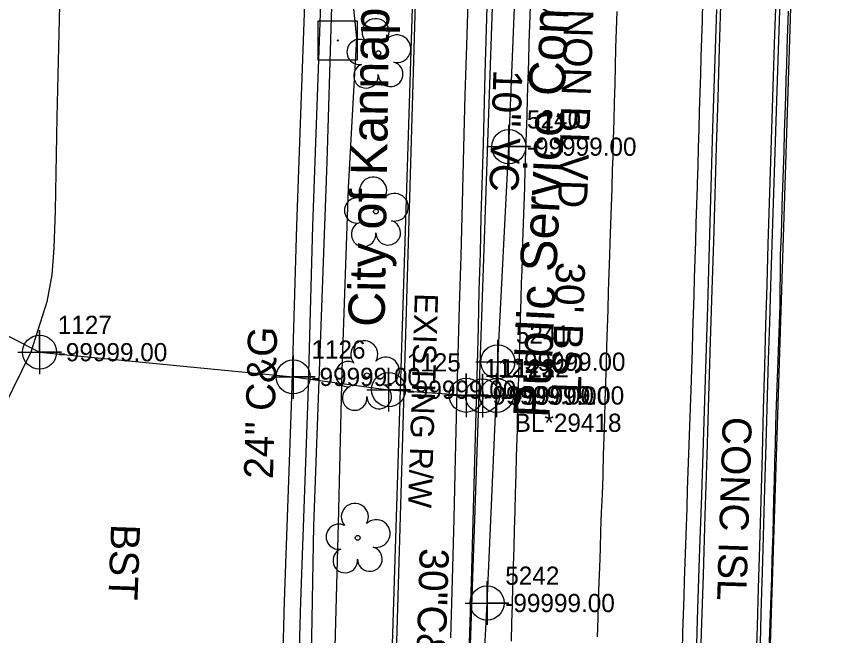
# Model space of a CAD drawing. Extents: x 1516784 to 1522736, y 634838 to 639369.
# Drawn here: x 1520333.4 to 1520444.6, y 637287.2 to 637372.3 of the extents above; entities that cross this region are included whole.
import ezdxf

# ---------------------------------------------------------------- set-up
doc = ezdxf.new("R2010")
doc.units = 0
for name, color, linetype in [('COGO Default Point Elevation', 7, 'Continuous'), ('COGO Default Point Number', 7, 'Continuous'), ('Exist Environmental Wetland Boundary Cogo Elevation', 7, 'Continuous'), ('Exist Environmental Wetland Boundary Cogo Number', 7, 'Continuous'), ('Exist Environmental Wetland Boundary Cogo Point CELL', 7, 'Continuous'), ('Exist Environmental Wetland Boundary Text', 7, 'Continuous'), ('Exist Right of Way Line', 7, 'Continuous'), ('Exist Right of Way Line Text', 7, 'Continuous'), ('Exist Roads Curbs Text', 7, 'Continuous'), ('Exist Roads EOP Other Text', 7, 'Continuous'), ('Exist Roads EOP Text', 7, 'Continuous'), ('Exist Utilities Gas UG Line SUE LOS B', 7, 'Continuous'), ('Exist Utilities Gas UG Line SUE LOS B Cogo Comment', 7, 'Continuous'), ('Exist Utilities Gas UG Line SUE LOS B Cogo Elevation', 7, 'Continuous'), ('Exist Utilities Gas UG Line SUE LOS B Cogo Number', 7, 'Continuous'), ('Exist Utilities Gas UG Line SUE LOS B Cogo Point CELL', 7, 'Continuous'), ('Exist Utilities Gas UG Line SUE LOS B Text', 7, 'Continuous'), ('Exist Utilities Other Pole With Base CELL', 7, 'Continuous'), ('Exist Utilities Sanitary Sewer UG Line', 7, 'Continuous'), ('Exist Utilities Sanitary Sewer UG Line Text', 7, 'Continuous'), ('Exist Utilities Water UG Line SUE LOS C', 7, 'Continuous'), ('Exist Utilities Water UG Line SUE LOS C Text', 7, 'Continuous'), ('Exist Vegetation Hedge Row', 7, 'Continuous'), ('Exist Vegetation Tree CELL', 7, 'Continuous'), ('Scratch_Level_5', 7, 'Continuous')]:
    doc.layers.add(name, color=color, linetype=linetype)

msp = doc.modelspace()

# ---------------------------------------------------------------- linework, layer by layer
at = {"layer": 'COGO Default Point Elevation'}
for points in [[(1520404.06, 637373.62), (1520403.98, 637371.12), (1520403.9, 637368.62), (1520403.82, 637366.13), (1520403.74, 637363.63), (1520403.67, 637361.13), (1520403.59, 637358.63), (1520403.51, 637356.32), (1520403.43, 637353.82), (1520403.35, 637351.32), (1520403.27, 637348.82), (1520403.18, 637346.33), (1520403.1, 637343.83), (1520403.02, 637341.33), (1520402.94, 637338.83), (1520402.85, 637336.34), (1520402.84, 637335.88), (1520402.77, 637333.38), (1520402.7, 637330.88), (1520402.63, 637328.38), (1520402.55, 637325.88), (1520402.48, 637323.39), (1520402.41, 637320.89), (1520402.34, 637318.39), (1520402.3, 637316.8), (1520402.23, 637314.31), (1520402.16, 637311.81), (1520402.09, 637309.31), (1520402.02, 637306.81), (1520401.94, 637304.32), (1520401.87, 637301.82), (1520401.8, 637299.32), (1520401.73, 637296.82), (1520401.66, 637294.32), (1520401.65, 637293.98), (1520401.58, 637291.48), (1520401.51, 637288.98), (1520401.43, 637286.48)], [(1520424.98, 637285.15), (1520425.06, 637287.65), (1520425.13, 637290.15), (1520425.21, 637292.64), (1520425.27, 637294.78), (1520425.36, 637297.27), (1520425.44, 637299.77), (1520425.53, 637302.27), (1520425.62, 637304.76), (1520425.7, 637307.26), (1520425.79, 637309.76), (1520425.88, 637312.26), (1520425.96, 637314.75), (1520426.05, 637317.25), (1520426.13, 637319.75), (1520426.22, 637322.25), (1520426.28, 637323.89), (1520426.35, 637326.39), (1520426.43, 637328.89), (1520426.51, 637331.39), (1520426.58, 637333.88), (1520426.66, 637336.38), (1520426.73, 637338.88), (1520426.81, 637341.38), (1520426.89, 637343.87), (1520426.96, 637346.37), (1520427.04, 637348.87), (1520427.05, 637349.26), (1520427.13, 637351.75), (1520427.2, 637354.25), (1520427.28, 637356.75), (1520427.35, 637359.25), (1520427.43, 637361.75), (1520427.51, 637364.24), (1520427.58, 637366.74), (1520427.66, 637369.24), (1520427.73, 637371.74), (1520427.81, 637374.24)], [(1520415.95, 637372.93), (1520415.88, 637370.44), (1520415.81, 637367.94), (1520415.74, 637365.44), (1520415.68, 637362.94), (1520415.61, 637360.44), (1520415.54, 637357.95), (1520415.47, 637355.45), (1520415.4, 637352.95), (1520415.35, 637351.19), (1520415.27, 637348.69), (1520415.18, 637346.19), (1520415.09, 637343.7), (1520415.01, 637341.2), (1520414.95, 637339.48), (1520414.87, 637336.99), (1520414.8, 637334.49), (1520414.72, 637331.99), (1520414.64, 637329.49), (1520414.57, 637327), (1520414.49, 637324.5), (1520414.42, 637322), (1520414.34, 637319.5), (1520414.27, 637317), (1520414.19, 637314.51), (1520414.11, 637312.01), (1520414.04, 637309.51), (1520414.03, 637309.13), (1520413.94, 637306.63), (1520413.84, 637304.14), (1520413.75, 637301.64), (1520413.66, 637299.14), (1520413.57, 637296.65), (1520413.49, 637294.58), (1520413.42, 637292.09), (1520413.34, 637289.59), (1520413.27, 637287.09)], [(1520439.5, 637372.97), (1520439.43, 637370.47), (1520439.35, 637367.97), (1520439.27, 637365.47), (1520439.22, 637363.75), (1520439.14, 637361.25), (1520439.06, 637358.75), (1520438.98, 637356.26), (1520438.9, 637353.76), (1520438.82, 637351.26), (1520438.74, 637348.76), (1520438.66, 637346.27), (1520438.58, 637343.77), (1520438.5, 637341.27), (1520438.44, 637339.54), (1520438.42, 637337.04), (1520438.39, 637334.54), (1520438.38, 637332.57), (1520438.29, 637330.07), (1520438.19, 637327.58), (1520438.1, 637325.08), (1520438.01, 637322.58), (1520437.92, 637320.09), (1520437.83, 637317.59), (1520437.78, 637316.05), (1520437.71, 637313.55), (1520437.65, 637311.05), (1520437.59, 637308.55), (1520437.52, 637306.06), (1520437.46, 637303.56), (1520437.4, 637301.06), (1520437.37, 637300.18), (1520437.29, 637297.68), (1520437.21, 637295.19), (1520437.12, 637292.69), (1520437.04, 637290.19), (1520436.96, 637287.69), (1520436.88, 637285.44)]]:
    msp.add_lwpolyline(points, dxfattribs=at)
at = {"layer": 'COGO Default Point Number'}
for points in [[(1520398.09, 637373.57), (1520397.85, 637364.38), (1520397.58, 637354.8), (1520397.3, 637344.85), (1520397.17, 637339.74), (1520397.03, 637334.61), (1520396.9, 637329.53), (1520396.77, 637324.5), (1520396.52, 637314.57), (1520396.25, 637304.61), (1520395.96, 637294.64), (1520395.65, 637284.9)], [(1520438.37, 637374.4), (1520438.07, 637364.89), (1520437.75, 637355.05), (1520437.42, 637345.23), (1520437.09, 637335.29), (1520436.94, 637330.23), (1520436.79, 637325.1), (1520436.5, 637315.14), (1520436.22, 637305.87), (1520435.97, 637297.51), (1520435.77, 637290.29), (1520435.61, 637284.12), (1520435.48, 637278.91), (1520435.46, 637269.2), (1520435.57, 637263.31), (1520435.75, 637255.63), (1520435.97, 637247.03), (1520436.2, 637238.41), (1520436.43, 637229.54), (1520436.66, 637220.17), (1520436.89, 637210.51), (1520437.03, 637205.14)], [(1520424.34, 637205.04), (1520424.59, 637212.95), (1520424.86, 637221.22), (1520425.16, 637229.46), (1520425.44, 637237.75), (1520425.72, 637246.14), (1520425.99, 637254.71), (1520426.27, 637263.45), (1520426.54, 637272.17), (1520426.81, 637280.82), (1520427.08, 637289.4), (1520427.35, 637297.92), (1520427.64, 637306.53), (1520427.93, 637315.23), (1520428.2, 637323.88), (1520428.46, 637332.44), (1520428.7, 637340.75), (1520428.92, 637348.82), (1520429.17, 637356.92), (1520429.44, 637365.09), (1520429.71, 637373.22)]]:
    msp.add_lwpolyline(points, dxfattribs=at)
at = {"layer": 'Exist Environmental Wetland Boundary Cogo Elevation'}
msp.add_lwpolyline([(1520332.04, 637433.25), (1520340.94, 637432.87), (1520339.42, 637375.76), (1520339.01, 637358.42), (1520338.8, 637345.6), (1520338.58, 637340.45), (1520338.33, 637336.8), (1520337.65, 637333.07), (1520335.42, 637326.18), (1520330.32, 637315.81), (1520324.72, 637306.87), (1520317.62, 637297.56), (1520313.49, 637293.52), (1520309.75, 637291.34), (1520305.26, 637289.8), (1520300.34, 637289.03), (1520295.68, 637289.02), (1520291.65, 637289.38)], dxfattribs=at)
at = {"layer": 'Exist Environmental Wetland Boundary Cogo Number'}
for points in [[(1520375.34, 637376.51), (1520374.17, 637343.49), (1520373.49, 637319.99), (1520372.48, 637291.92), (1520371.83, 637267.31), (1520357.88, 637267.61), (1520356.33, 637267.53), (1520355.14, 637266.38), (1520354.69, 637264.71), (1520354.4, 637259.13)], [(1520437.85, 637375.73), (1520437.66, 637369.85), (1520437.47, 637364.01), (1520437.28, 637358.19), (1520437.09, 637352.41), (1520436.91, 637346.67), (1520436.74, 637341), (1520436.58, 637335.39), (1520436.42, 637329.86), (1520436.26, 637324.22), (1520436.1, 637318.34), (1520435.93, 637312.2), (1520435.75, 637305.81), (1520435.57, 637299.53), (1520435.4, 637293.75), (1520435.24, 637288.45), (1520434.95, 637279.56)], [(1520395.55, 637375.66), (1520395.31, 637368.33), (1520395.09, 637361.45), (1520394.9, 637354.23), (1520394.72, 637346.64), (1520394.53, 637339.37), (1520394.31, 637332.51), (1520394.12, 637325.81), (1520393.95, 637319.11), (1520393.77, 637311.6), (1520393.57, 637303.27), (1520393.34, 637294.96), (1520393.1, 637286.93)], [(1520425.34, 637218.9), (1520425.55, 637225.26), (1520425.76, 637231.73), (1520425.98, 637238.21), (1520426.2, 637244.69), (1520426.43, 637251.18), (1520426.65, 637257.84), (1520426.89, 637264.82), (1520427.12, 637272.12), (1520427.36, 637279.75), (1520427.61, 637287.61), (1520427.86, 637295.6), (1520428.11, 637303.72), (1520428.37, 637311.98), (1520428.63, 637320.06), (1520428.86, 637327.64), (1520429.08, 637334.74), (1520429.28, 637341.34), (1520429.48, 637347.77), (1520429.68, 637354.34), (1520429.89, 637361.05), (1520430.1, 637367.9), (1520430.33, 637375.28)]]:
    msp.add_lwpolyline(points, dxfattribs=at)
at = {"layer": 'Exist Environmental Wetland Boundary Cogo Point CELL'}
msp.add_lwpolyline([(1520376.57, 637480.17), (1520375.98, 637461.88), (1520375.36, 637442.8), (1520374.43, 637420.34), (1520373.76, 637395.96), (1520373.12, 637376.59), (1520371.96, 637343.56), (1520371.28, 637320.07), (1520370.26, 637291.99), (1520369.67, 637269.57), (1520357.85, 637269.82), (1520355.39, 637269.7), (1520353.16, 637267.55), (1520352.49, 637265.06), (1520352.21, 637259.8)], dxfattribs=at)
at = {"layer": 'Exist Environmental Wetland Boundary Text'}
msp.add_line((1520460.36, 638022.61), (1520433.58, 637175.96), dxfattribs=at)
at = {"layer": 'Exist Right of Way Line'}
msp.add_line((1520392.38, 637516.53), (1520383.93, 637249.27), dxfattribs=at)
at = {"layer": 'Exist Utilities Gas UG Line SUE LOS B'}
for points in [[(1520395.28, 637209.93), (1520395.83, 637233.81), (1520396.63, 637263.16), (1520398.14, 637291.72), (1520399.6, 637324.85), (1520401.12, 637354.38), (1520402.42, 637385.79)], [(1520308.77, 637341.99), (1520314.56, 637337.54), (1520336.64, 637326.16), (1520371.5, 637322.77), (1520384.6, 637321.01), (1520395.27, 637320.24), (1520397.5, 637320.17), (1520399.43, 637320.22)]]:
    msp.add_lwpolyline(points, dxfattribs=at)
at = {"layer": 'Exist Utilities Gas UG Line SUE LOS B Cogo Point CELL'}
for points in [[(1520398.12, 637354.38), (1520404.12, 637354.38), (1520401.12, 637354.38), (1520401.12, 637357.38), (1520401.12, 637351.38)], [(1520333.64, 637326.16), (1520339.64, 637326.16), (1520336.64, 637326.16), (1520336.64, 637329.16), (1520336.64, 637323.16)], [(1520396.6, 637324.85), (1520402.6, 637324.85), (1520399.6, 637324.85), (1520399.6, 637327.85), (1520399.6, 637321.85)], [(1520368.5, 637322.77), (1520374.5, 637322.77), (1520371.5, 637322.77), (1520371.5, 637325.77), (1520371.5, 637319.77)], [(1520381.6, 637321.01), (1520387.6, 637321.01), (1520384.6, 637321.01), (1520384.6, 637324.01), (1520384.6, 637318.01)], [(1520392.27, 637320.24), (1520398.27, 637320.24), (1520395.27, 637320.24), (1520395.27, 637323.24), (1520395.27, 637317.24)], [(1520394.5, 637320.17), (1520400.5, 637320.17), (1520397.5, 637320.17), (1520397.5, 637323.17), (1520397.5, 637317.17)], [(1520396.43, 637320.22), (1520402.43, 637320.22), (1520399.43, 637320.22), (1520399.43, 637323.22), (1520399.43, 637317.22)], [(1520395.14, 637291.72), (1520401.14, 637291.72), (1520398.14, 637291.72), (1520398.14, 637294.72), (1520398.14, 637288.72)]]:
    msp.add_lwpolyline(points, dxfattribs=at)
for centre in [(1520401.12, 637354.38), (1520336.64, 637326.16), (1520399.6, 637324.85), (1520371.5, 637322.77), (1520384.6, 637321.01), (1520395.27, 637320.24), (1520397.5, 637320.17), (1520399.43, 637320.22), (1520398.14, 637291.72)]:
    msp.add_circle(centre, 2.34, dxfattribs=at)
at = {"layer": 'Exist Utilities Other Pole With Base CELL'}
msp.add_line((1520377.63, 637368.97), (1520377.63, 637368.97), dxfattribs=at)
msp.add_lwpolyline([(1520374.91, 637371.67), (1520380.31, 637371.67), (1520380.31, 637366.27), (1520374.91, 637366.27), (1520374.91, 637371.67)], dxfattribs=at)
msp.add_circle((1520377.63, 637368.97), 0.0707, dxfattribs=at)
at = {"layer": 'Exist Utilities Sanitary Sewer UG Line'}
msp.add_line((1520401.19, 637442.63), (1520394.09, 637235.13), dxfattribs=at)
at = {"layer": 'Exist Utilities Water UG Line SUE LOS C'}
msp.add_lwpolyline([(1520382.58, 637189.84), (1520384.26, 637236.31), (1520393.57, 637554.04), (1520396.87, 637710.27)], dxfattribs=at)
at = {"layer": 'Exist Vegetation Hedge Row'}
for points in [[(1520356.47, 637266.55), (1520373.67, 637266.52), (1520374.33, 637302.32), (1520376.18, 637352.29), (1520377.35, 637391.98)], [(1520379.39, 637377.44), (1520380.21, 637369.28), (1520379.7, 637360.36), (1520379.03, 637348.72), (1520378.2, 637323.64), (1520377.68, 637302.65), (1520377.16, 637284.01), (1520376.63, 637271.06), (1520377.02, 637262.25), (1520375.52, 637257.71), (1520370.26, 637255.31), (1520365.22, 637255.35), (1520362.68, 637259.82), (1520362.01, 637263.57), (1520355.98, 637264.16), (1520356.47, 637266.55)]]:
    msp.add_lwpolyline(points, dxfattribs=at)
at = {"layer": 'Exist Vegetation Tree CELL'}
for p, q in [((1520383.2, 637367.23), (1520383.2, 637367.23)), ((1520382.87, 637345.47), (1520382.87, 637345.47)), ((1520381.64, 637322.99), (1520381.64, 637322.99)), ((1520380.36, 637300.67), (1520380.36, 637300.67))]:
    msp.add_line(p, q, dxfattribs=at)
for centre in [(1520383.2, 637367.23), (1520382.87, 637345.47), (1520381.64, 637322.99), (1520380.36, 637300.67)]:
    msp.add_circle(centre, 0.326, dxfattribs=at)
for centre, radius, start, end in [((1520382.82, 637370.1), 1.86, 330.1651, 219.7134), ((1520380.6, 637367.38), 1.73, 62.6636, 279.3457), ((1520385.75, 637367.82), 1.9, 257.1011, 134.1999), ((1520384.88, 637364.33), 1.7, 181.2822, 74.56), ((1520381.5, 637364.11), 1.69, 111.5671, 6.231), ((1520382.49, 637348.34), 1.86, 330.1651, 219.7134), ((1520385.42, 637346.06), 1.9, 257.1011, 134.1999), ((1520380.27, 637345.62), 1.73, 62.6636, 279.3457), ((1520381.17, 637342.35), 1.69, 111.5671, 6.231), ((1520384.55, 637342.57), 1.7, 181.2822, 74.56), ((1520381.26, 637325.86), 1.86, 330.1651, 219.7134), ((1520379.04, 637323.15), 1.73, 62.6636, 279.3457), ((1520384.19, 637323.58), 1.9, 257.1011, 134.1999), ((1520379.94, 637319.87), 1.69, 111.5671, 6.231), ((1520383.31, 637320.09), 1.7, 181.2822, 74.56), ((1520379.97, 637303.54), 1.86, 330.1651, 219.7134), ((1520377.75, 637300.82), 1.73, 62.6636, 279.3457), ((1520382.91, 637301.26), 1.9, 257.1011, 134.1999), ((1520378.65, 637297.55), 1.69, 111.5671, 6.231), ((1520382.03, 637297.77), 1.7, 181.2822, 74.56)]:
    msp.add_arc(centre, radius, start, end, dxfattribs=at)

# ---------------------------------------------------------------- texts
at = {"layer": 'Exist Right of Way Line Text'}
msp.add_text('EXISTING R/W', height=3.2, rotation=268.1887, dxfattribs=at).set_placement((1520388.22, 637334.29))
at = {"layer": 'Exist Roads Curbs Text'}
for s, rotation, p in [('24" C&G', 88.3471, (1520368.71, 637308.71)), ('CONC ISL', 268.197, (1520430.54, 637317.33)), ('30"C&G', 268.253, (1520388.9, 637299.29))]:
    msp.add_text(s, height=4, rotation=rotation, dxfattribs=at).set_placement(p)
at = {"layer": 'Exist Roads EOP Other Text'}
msp.add_text('BST', height=4, rotation=267.9794, dxfattribs=at).set_placement((1520346.47, 637302.6))
at = {"layer": 'Exist Roads EOP Text'}
msp.add_text("U2 29 S CANNON BLVD     30' BST", height=4, rotation=268.125, dxfattribs=at).set_placement((1520409.82, 637405.42))
at = {"layer": 'Exist Utilities Gas UG Line SUE LOS B Cogo Comment'}
msp.add_text('BL*29418', height=2.5, dxfattribs=at).set_placement((1520401.93, 637315.22))
at = {"layer": 'Exist Utilities Gas UG Line SUE LOS B Cogo Elevation'}
for p in [(1520403.62, 637353.13), (1520339.14, 637324.91), (1520402.1, 637323.6), (1520374, 637321.52), (1520387.1, 637319.76), (1520397.77, 637318.99), (1520400, 637318.92), (1520401.93, 637318.97), (1520400.64, 637290.47)]:
    msp.add_text('-99999.00', height=2.5, dxfattribs=at).set_placement(p)
at = {"layer": 'Exist Utilities Gas UG Line SUE LOS B Cogo Number'}
for s, p in [('5240', (1520403.62, 637356.88)), ('1127', (1520339.14, 637328.66)), ('5241', (1520402.1, 637327.35)), ('1126', (1520374, 637325.27)), ('1125', (1520387.1, 637323.51)), ('1124', (1520397.77, 637322.74)), ('1123', (1520400, 637322.67)), ('1122', (1520401.93, 637322.72)), ('5242', (1520400.64, 637294.22))]:
    msp.add_text(s, height=2.5, dxfattribs=at).set_placement(p)
at = {"layer": 'Exist Utilities Gas UG Line SUE LOS B Text'}
msp.add_text('Public Service Company Of N C Inc., 6 ", Steel', height=5, rotation=87.3152, dxfattribs=at).set_placement((1520406.71, 637317.05))
at = {"layer": 'Exist Utilities Sanitary Sewer UG Line Text'}
msp.add_text('10" VC', height=4, rotation=268.0416, dxfattribs=at).set_placement((1520399.02, 637364.99))
at = {"layer": 'Exist Utilities Water UG Line SUE LOS C Text'}
msp.add_text('City of Kannapolis, Unknown Type 8"', height=5, rotation=89.1508, dxfattribs=at).set_placement((1520384.06, 637329.6))
at = {"layer": 'Scratch_Level_5'}
msp.add_text('COLUMN LOCATION', height=500, rotation=335.0373, dxfattribs=at).set_placement((1516680.97, 637558.94))

doc.saveas('drawing.dxf')
